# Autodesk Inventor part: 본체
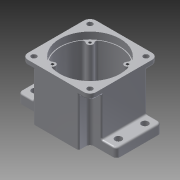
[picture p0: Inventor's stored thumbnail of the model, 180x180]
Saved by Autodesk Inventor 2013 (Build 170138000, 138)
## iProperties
Created: 2015-07
Part Number: 본체
Material: 알루미늄 6061
Document SubType Name: Modeling
Designer: user
Density: 1 g/cm^3
Author: user
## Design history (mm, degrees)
sketch "스케치1"
  geometry: L1 (-65, 30)-(65, 30); L2 (65, 30)-(65, -30); L3 (65, -30)-(-65, -30); L4 (-65, -30)-(-65, 30); L5 (-45, 45)-(45, 45); L6 (45, 45)-(45, -45); L7 (45, -45)-(-45, -45); L8 (-45, -45)-(-45, 45); 5 further points
  constraints: 16 end point, 4 midpoint, 4 parallel, 2 horizontal, 2 horizontal alignment, 2 perpendicular, 2 vertical alignment
  dimensions: "d0" = 130 distance of L2.end L3.end; "d1" = 60 distance of L1.end L2.end; "d2" = 90 distance of L6.end L7.end; "d3" = 90 distance of L5.end L6.end
extrude "돌출1" new body sketch "스케치1" distance "d4" = 12; taper "d5" = 0 deg
extrude "돌출2" join sketch "스케치1" distance "d6" = 70; taper "d7" = 0 deg
sketch "스케치2"
  geometry: L1 (-45, -45)-(45, -45) reference; L2 (65, -30)-(65, 30) reference; L3 (65, 30)-(45, 30) reference; L4 (45, 30)-(45, 45) reference; L5 (45, 45)-(-45, 45) reference; L6 (-45, 45)-(-45, 30) reference; L7 (45, 45)-(30, 45); L8 (30, 45)-(30, 30); L9 (30, 30)-(45, 30); L10 (45, 30)-(45, 45); L11 (45, -45)-(45, -30); L12 (30, -45)-(45, -45); L13 (45, -30)-(30, -30); L14 (30, -30)-(30, -45); L15 (-30, -30)-(-45, -30); L16 (-30, -45)-(-30, -30); L17 (-45, -30)-(-45, -45); L18 (-45, -45)-(-30, -45); L19 (-30, 45)-(-45, 45); L20 (-30, 30)-(-30, 45); L21 (-45, 30)-(-30, 30); L22 (-45, 45)-(-45, 30); 1 further point
  constraints: 32 end point, 6 parallel, 5 collinear, 3 perpendicular, 1 point on line
  dimensions: "d8" = 15 distance of L4.end L7.end; "d9" = 15 distance of L7.end L8.end; "d10" = 15 distance of L8.end L3.end (derived); "d11" = 15 distance of L11.end L13.end; "d12" = 15 distance of L13.end L12.start; "d13" = 15 distance of L12.start L11.start (derived); "d14" = 15 distance of L15.start L15.end; "d15" = 15 distance of L15.end L17.end; "d16" = 15 distance of L17.end L16.start (derived); "d17" = 15 distance of L19.start L19.end; "d18" = 15 distance of L19.end L21.start; "d19" = 15 distance of L21.start L20.start (derived); "d20" = 60 distance between parallel lines of L3 L13; "d21" = 20 distance between parallel lines of L2 L11; "d22" = 0 distance between parallel lines of L5 L19; "d23" = 75 distance between parallel lines of L5 L15; "d24" = 15 distance between parallel lines of L6 L16; "d25" = 95 distance between parallel lines of L20 L2
extrude "돌출3" cut sketch "스케치2" distance "d26" = 63; taper "d27" = 0 deg
sketch "스케치3"
  geometry: C1 r 40 at (0, 0); 1 further point
  constraints: 1 centre point, 1 coincident
  dimensions: "d28" = 80 diameter of C1
extrude "돌출4" cut sketch "스케치3" distance "d29" = 9; taper "d30" = 0 deg
sketch "스케치4"
  geometry: C1 r 40 at (0, 0) reference; C2 r 39 at (0, 0)
  constraints: 1 centre point, 1 coincident
  dimensions: "d31" = 78 diameter of C2
extrude "돌출5" cut sketch "스케치4" distance "d32" = 52; taper "d33" = 0 deg
node "작업 평면1"
sketch "스케치5"
  geometry: L1 (30, -30)-(30, -45) reference; L2 (30, -45)-(-30, -45) reference; L3 (-30, -45)-(-30, -30) reference; L4 (-30, -30)-(-65, -30) reference; L5 (-65, -30)-(-65, 30) reference; L6 (-65, 30)-(-30, 30) reference; L7 (-30, 30)-(-30, 45) reference; L8 (-30, 45)-(30, 45) reference; L9 (30, 45)-(30, 30) reference; L10 (30, 30)-(65, 30) reference; L11 (65, 30)-(65, -30) reference; L12 (65, -30)-(30, -30) reference; L13 (45, 45)-(30, 45) reference; L14 (45, 30)-(45, 45) reference; L15 (30, 30)-(45, 30) reference; L16 (30, 45)-(30, 30) reference; L17 (-45, 45)-(-45, 30) reference; L18 (-30, 45)-(-45, 45) reference; L19 (-30, 30)-(-30, 45) reference; L20 (-45, 30)-(-30, 30) reference; L21 (-45, -45)-(-30, -45) reference; L22 (-45, -30)-(-45, -45) reference; L23 (-30, -30)-(-45, -30) reference; L24 (-30, -45)-(-30, -30) reference; L25 (45, -30)-(30, -30) reference; L26 (45, -45)-(45, -30) reference; L27 (30, -45)-(45, -45) reference; L28 (30, -30)-(30, -45) reference; L29 (0, 0)-(0, 11); C1 r 25 at (0, 11)
  constraints: 2 end point, 1 centre point, 1 coincident, 1 parallel
  dimensions: "d35" = 11 distance of L29.start L29.end; "d36" = 50 diameter of C1
extrude "돌출6" join sketch "스케치5" stored distance "d37" = 8; taper "d38" = 0 deg
sketch "스케치6"
  geometry: C1 r 25 at (0, 0) reference; C2 r 20.5 at (0, 0); 1 further point
  constraints: 1 centre point, 1 coincident
  dimensions: "d39" = 20.5 radius of C2
extrude "돌출7" join sketch "스케치6" distance "d40" = 23; taper "d41" = 0 deg
sketch "스케치7"
  geometry: L1 (-65, -30)-(-30, -30) reference; L2 (0, 0)-(0, -20); C1 r 14 at (0, -20)
  constraints: 2 end point, 1 centre point, 1 coincident, 1 perpendicular
  dimensions: "d42" = 20 distance of L2.start L2.end; "d43" = 14 radius of C1
extrude "돌출8" join sketch "스케치7" distance "d44" = 16; taper "d45" = 0 deg
sketch "스케치8"
  geometry: C1 r 17.5 at (0, 0); A1 r 20.5 centre (0, 0) between (7.402, -19.117) and (-7.402, -19.117) reference; 1 further point
  constraints: 1 centre point, 1 coincident
  dimensions: "d46" = 35 diameter of C1
extrude "돌출9" cut sketch "스케치8" distance "d47" = 10; taper "d48" = 0 deg
sketch "스케치9"
  geometry: C1 r 17.5 at (0, 0) reference; C2 r 12.5 at (0, 0); 1 further point
  constraints: 1 centre point, 1 coincident
  dimensions: "d49" = 25 diameter of C2
extrude "돌출10" cut sketch "스케치9" distance "d50" = 5; taper "d51" = 0 deg
sketch "스케치10"
  geometry: C1 r 12.5 at (0, 0) reference; C2 r 16 at (0, 0); 1 further point
  constraints: 1 centre point, 1 coincident
  dimensions: "d52" = 32 diameter of C2
extrude "돌출11" cut sketch "스케치10" distance "d53" = 8; taper "d54" = 0 deg
sketch "스케치11"
  geometry: C1 r 11 at (0, -31); A1 r 14 centre (0, -31) between (-7.402, -19.117) and (7.402, -19.117) reference; 1 further point
  constraints: 1 centre point, 1 coincident
  dimensions: "d55" = 22 diameter of C1
extrude "돌출12" cut sketch "스케치11" distance "d56" = 7; taper "d57" = 0 deg
sketch "스케치12"
  geometry: C1 r 11 at (0, 0) reference; C2 r 9.5 at (0, 0); 1 further point
  constraints: 1 centre point, 1 coincident
  dimensions: "d58" = 19 diameter of C2
extrude "돌출13" cut sketch "스케치12" distance "d59" = 1; taper "d60" = 0 deg
fillet "모깎기1" dims "d61" = 0.3
fillet "모깎기2" dims "d62" = 2
fillet "모깎기3" dims "d63" = 5
fillet "모깎기4" dims "d64" = 8
fillet "모깎기5" dims "d65" = 5
sketch "스케치13"
  geometry: L1 (0, 0)-(35, 0); L2 (0, 0)-(24.749, 24.749); L3 (28.284, 28.284)-(31.726, 31.726); A1 r 39 centre (0, 0) between (21.134, 32.777) and (32.777, 21.134) reference; A2 r 4 centre (24.749, 24.749) between (21.809, 27.462) and (27.462, 21.809); A3 r 3.5 centre (19.238, 29.836) between (21.809, 27.462) and (21.134, 32.777); A4 r 3.5 centre (29.836, 19.238) between (32.777, 21.134) and (27.462, 21.809); 1 further point
  constraints: 8 point on circle, 6 end point, 5 tangent, 3 centre point, 2 coincident, 1 collinear, 1 horizontal, 2 other
  dimensions: "d69" = 4 radius of A2; "d70" = 3.5 radius of A3; "d71" = 45 deg angle of L1 L2; "d72" = 3.5 radius of A4; "d73" = 0 distance between parallel lines of L2 L3; "d74" = 44.86791 distance of point (0, 0) L3.end
extrude "돌출14" join sketch "스케치13" stored distance "d75" = 1; taper "d76" = 0 deg
sketch "스케치14"
  geometry: A1 r 4 centre (24.749, 24.749) between (21.809, 27.462) and (27.462, 21.809) reference; A2 r 4 centre (24.749, -24.749) between (27.462, -21.809) and (21.809, -27.462) reference; A3 r 4 centre (-24.749, -24.749) between (-21.809, -27.462) and (-27.462, -21.809) reference; A4 r 4 centre (-24.749, 24.749) between (-27.462, 21.809) and (-21.809, 27.462) reference
hole "구멍1" sketch "스케치14" at (-24.749, 24.749), (-24.749, -24.749), (24.749, -24.749), (24.749, 24.749) diameter "d80" = 3.459; stored, may be unused: countersink angle "d84" = 90 deg, drill point angle "d86" = 118 deg; dims "d81" = 12, "d82" = 4, "d83" = 2, "d85" = 15
sketch "스케치15"
  geometry: L1 (-37, 37)-(37, 37); L2 (37, 37)-(37, -37); L3 (37, -37)-(-37, -37); L4 (-37, -37)-(-37, 37); C1 r 40 at (0, 0) reference; A1 r 8 centre (37, -37) between (37, -45) and (45, -37) reference; A2 r 8 centre (-37, 37) between (-37, 45) and (-45, 37) reference; A3 r 8 centre (-37, -37) between (-45, -37) and (-37, -45) reference; 2 further points
  constraints: 8 end point, 2 midpoint, 2 parallel, 1 horizontal, 1 horizontal alignment, 1 perpendicular, 1 vertical alignment
  dimensions: "d87" = 74 distance of L2.end L3.end; "d88" = 74 distance of L3.end L1.start
hole "구멍2" sketch "스케치15" at (-37, 37), (37, 37), (37, -37), (-37, -37) diameter "d89" = 7; stored, may be unused: countersink angle "d93" = 90 deg, drill point angle "d95" = 118 deg; dims "d90" = 12, "d91" = 4, "d92" = 2, "d94" = 7
sketch "스케치16"
  geometry: L1 (-55, 17.5)-(55, 17.5); L2 (55, 17.5)-(55, -17.5); L3 (55, -17.5)-(-55, -17.5); L4 (-55, -17.5)-(-55, 17.5); 3 further points
  constraints: 8 end point, 2 midpoint, 2 parallel, 1 horizontal, 1 horizontal alignment, 1 perpendicular, 1 vertical alignment
  dimensions: "d96" = 110 distance of L2.end L3.end; "d97" = 35 distance of L1.end L2.end
hole "구멍3" sketch "스케치16" at (-55, 17.5), (-55, -17.5), (55, 17.5), (55, -17.5) diameter "d98" = 9; stored, may be unused: countersink angle "d102" = 90 deg, drill point angle "d104" = 118 deg; dims "d99" = 12, "d100" = 4, "d101" = 2, "d103" = 7
fillet "모깎기7" dims "d106" = 3
fillet "모깎기8" dims "d107" = 2
chamfer "모따기1" distance "d109" = 1; stored, may be unused: second distance "d110" = 2, angle "d111" = 45 deg
sketch "스케치17"
  geometry: L1 (-30, -45)-(30, -45) reference; 4 further points
  constraints: 1 vertical alignment, 1 other
  dimensions: "d112" = 15 distance from line of L1 point (0, -30)
feature "엠보싱1" sketch "스케치17" dims "d113" = 0.5, "d114" = 0
fillet "모깎기10" dims "d115" = 2
fillet "모깎기11" dims "d116" = 2
fillet "모깎기12" dims "d117" = 2
fillet "모깎기13" dims "d118" = 2
node "솔리드1"
pattern_circular "원형 패턴1" dims angle "d78" = 360 deg
node "투영된 루프1"
node "투영된 루프2"
node "투영된 루프3"
node "투영된 루프4"
node "투영된 루프5"
other parameters: "d34" = -7, "d67" = 45 deg
